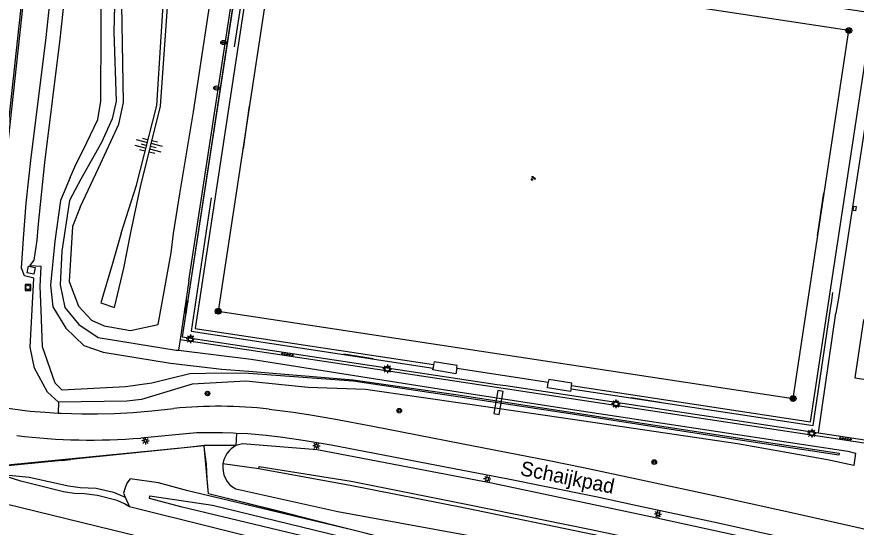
# Model space of a CAD drawing. Extents: x 125000 to 129004, y 397500 to 399008.
# Drawn here: x 126193.2 to 126337.5, y 398746.2 to 398833.9 of the extents above; entities that cross this region are included whole.
import ezdxf

# ---------------------------------------------------------------- set-up
doc = ezdxf.new("R2010")
doc.units = 0
for name, color, linetype in [('bs-afsc-ballenvanger', 7, 'Continuous'), ('bs-afsc-belijning', 7, 'Continuous'), ('bs-afsc-doel', 7, 'Continuous'), ('bs-afsc-hekwerk laag', 7, 'Continuous'), ('bs-afsc-poort', 7, 'Continuous'), ('bs-symb-cornervlag', 7, 'Continuous'), ('bs-symb-veldverlichting', 7, 'Continuous'), ('gg-afsc-hekwerk', 7, 'Continuous'), ('gg-anno-openbare ruimte label', 7, 'Continuous'), ('gg-aspt-spoorlijn', 7, 'Continuous'), ('gg-bbg-overig bouwwerk', 7, 'Continuous'), ('gg-knt-BGT kruinlijn', 7, 'Continuous'), ('gg-knt-bovenkant onderkant talud', 7, 'Continuous'), ('gg-knt-verharding', 7, 'Continuous'), ('gg-kntw-bovenkant insteek waterloop', 7, 'Continuous'), ('gg-kntw-waterlijn', 7, 'Continuous'), ('gg-kwrk-kunstwerk', 7, 'Continuous'), ('gg-kwrk-kunstwerk niveau 01', 7, 'Continuous'), ('gg-kwrk-uitstroombak niveau min 01', 7, 'Continuous'), ('gt-grn-groengrens', 7, 'Continuous'), ('gt-symb-boom', 7, 'Continuous'), ('gt-symb-drainageput', 7, 'Continuous'), ('gt-symb-groenvak', 7, 'Continuous'), ('gt-symb-kolk center center', 7, 'Continuous'), ('gt-symb-lichtmast', 7, 'Continuous'), ('gt-symb-rioolschacht', 7, 'Continuous'), ('gt-symb-talud symbool', 7, 'Continuous'), ('gt-symb-tegel verharding', 7, 'Continuous'), ('gx-grn-maaiveld', 7, 'Continuous')]:
    doc.layers.add(name, color=color, linetype=linetype)

# ---------------------------------------------------------------- blocks, each defined once
blk = doc.blocks.new('bs0-CORNVLG')
at = {"layer": 'bs-symb-cornervlag'}
for p, q in [((-0.34, 0.2), (0.2, -0.34)), ((-0.21, 0.35), (0.34, -0.2)), ((0.03, 0.4), (0.4, 0.03)), ((-0.4, -0.03), (-0.03, -0.4))]:
    blk.add_line(p, q, dxfattribs=at)
blk.add_circle((0, 0), 0.5, dxfattribs=at)
blk = doc.blocks.new('bs0-VELDV')
at = {"layer": 'bs-symb-veldverlichting'}
for p, q in [((-0.38, 0), (-0.75, 0)), ((-0.53, 0.53), (-0.27, 0.27)), ((-0.35, 0.14), (-0.52, 0.22)), ((-0.22, 0.52), (-0.14, 0.35)), ((0, 0.75), (0, 0.38)), ((0.22, 0.52), (0.14, 0.35)), ((0.27, 0.27), (0.53, 0.53)), ((0.35, 0.14), (0.52, 0.22)), ((0.38, 0), (0.75, 0)), ((-0.27, -0.27), (-0.53, -0.53)), ((-0.35, -0.14), (-0.52, -0.22)), ((-0.14, -0.35), (-0.22, -0.52)), ((0, -0.38), (0, -0.75)), ((0.14, -0.35), (0.22, -0.52)), ((0.27, -0.27), (0.53, -0.53)), ((0.35, -0.14), (0.52, -0.22))]:
    blk.add_line(p, q, dxfattribs=at)
blk.add_circle((0, 0), 0.375, dxfattribs=at)
blk = doc.blocks.new('gt0-TEG1')
at = {"layer": 'gt-symb-tegel verharding'}
for p, q in [((-1.12, 0), (1.12, 0)), ((-0.9, -0.25), (-0.9, 0.25)), ((-0.45, -0.25), (-0.45, 0.25)), ((0, -0.25), (0, 0.25)), ((0.45, -0.25), (0.45, 0.25)), ((0.9, -0.25), (0.9, 0.25))]:
    blk.add_line(p, q, dxfattribs=at)
blk = doc.blocks.new('gt0-KOLKCC')
at = {"layer": 'gt-symb-kolk center center'}
blk.add_lwpolyline([(-0.38, 0.2), (0.37, 0.2), (0.37, -0.2), (-0.38, -0.2)], close=True, dxfattribs=at)
blk = doc.blocks.new('gt0-GRVAK')
at = {"layer": 'gt-symb-groenvak'}
for p, q in [((-0.11, 0.19), (-0.23, 0.24)), ((-0.18, 0.15), (0.09, 0.15)), ((-0.09, 0.21), (-0.16, 0.32)), ((-0.05, 0.21), (-0.05, 0.39)), ((0, 0.21), (0.06, 0.32)), ((0.01, 0.19), (0.13, 0.24)), ((0.26, -0.05), (0.2, 0.06)), ((0.3, -0.05), (0.3, 0.13)), ((0.35, -0.05), (0.41, 0.06)), ((-0.24, -0.23), (-0.36, -0.18)), ((-0.32, -0.26), (-0.05, -0.26)), ((-0.23, -0.21), (-0.29, -0.09)), ((-0.18, -0.2), (-0.18, -0.02)), ((-0.14, -0.21), (-0.07, -0.09)), ((-0.12, -0.23), (0, -0.18)), ((0.24, -0.07), (0.12, -0.02)), ((0.17, -0.11), (0.44, -0.11)), ((0.37, -0.07), (0.49, -0.02))]:
    blk.add_line(p, q, dxfattribs=at)
blk = doc.blocks.new('gt0-LMAST')
at = {"layer": 'gt-symb-lichtmast'}
for p, q in [((-0.18, 0.17), (-0.45, 0.44)), ((-0.01, 0.25), (-0.01, 0.62)), ((0.17, 0.17), (0.44, 0.44)), ((-0.26, 0), (-0.63, 0)), ((-0.18, -0.18), (-0.45, -0.45)), ((-0.01, -0.25), (-0.01, -0.63)), ((0.44, -0.45), (0.17, -0.18)), ((0.24, 0), (0.62, 0))]:
    blk.add_line(p, q, dxfattribs=at)
blk.add_circle((-0.01, 0), 0.25, dxfattribs=at)
blk = doc.blocks.new('gt0-BOOM')
at = {"layer": 'gt-symb-boom'}
for radius in [0.4, 0.2]:
    blk.add_circle((0, 0), radius, dxfattribs=at)
blk = doc.blocks.new('gt0-DPUT')
at = {"layer": 'gt-symb-drainageput'}
for p, q in [((-0.25, 0.05), (0.25, 0.05)), ((0.24, -0.05), (-0.25, -0.05))]:
    blk.add_line(p, q, dxfattribs=at)
for centre, radius, start, end in [((-0.25, 0), 0.0542, 85.4775, 270), ((0.24, 0), 0.0543, 269.9965, 85.474)]:
    blk.add_arc(centre, radius, start, end, dxfattribs=at)
blk.add_ellipse((0, 0), major_axis=(0.502, 0), ratio=0.705307, dxfattribs=at)
blk = doc.blocks.new('gt0-RS')
at = {"layer": 'gt-symb-rioolschacht'}
blk.add_lwpolyline([(-0.5, -0.5), (0.5, -0.5), (0.5, 0.5), (-0.5, 0.5)], close=True, dxfattribs=at)
blk.add_circle((0, 0), 0.375, dxfattribs=at)
blk = doc.blocks.new('gt0-TALUD_1')
at = {"layer": 'gt-symb-talud symbool'}
for p, q in [((-1, -1), (-1, 0)), ((-0.5, -2), (-0.5, 0)), ((0, -1), (0, 0)), ((0.5, -2), (0.5, 0)), ((1, -1), (1, 0))]:
    blk.add_line(p, q, dxfattribs=at)

msp = doc.modelspace()

# ---------------------------------------------------------------- linework, layer by layer
at = {"layer": 'bs-afsc-ballenvanger'}
msp.add_line((126341.93, 398834.46), (126334.44, 398785.6), dxfattribs=at)
for points in [[(126233, 398853.21), (126221.64, 398778.96), (126275.77, 398770.77)], [(126277.25, 398770.55), (126330.99, 398762.42), (126333.99, 398783.02)]]:
    msp.add_lwpolyline(points, dxfattribs=at)
at = {"layer": 'bs-afsc-belijning'}
msp.add_lwpolyline([(126237.42, 398846.56), (126227.83, 398783.32), (126326.65, 398768.33), (126336.23, 398831.55), (126237.42, 398846.56)], dxfattribs=at)
at = {"layer": 'bs-afsc-doel'}
for p, q in [((126233.16, 398818.61), (126232.1, 398811.22)), ((126330.82, 398796.27), (126331.94, 398803.64)), ((126249.44, 398776), (126254.46, 398775.23)), ((126298.81, 398768.51), (126303.82, 398767.74))]:
    msp.add_line(p, q, dxfattribs=at)
at = {"layer": 'bs-afsc-hekwerk laag'}
for p, q in [((126234.04, 398851.18), (126230.58, 398828.74)), ((126333.28, 398785.15), (126333.49, 398786.54))]:
    msp.add_line(p, q, dxfattribs=at)
for points in [[(126226.64, 398802.81), (126223.19, 398779.89), (126264.76, 398773.55)], [(126288.47, 398770.03), (126330.07, 398763.72), (126333.06, 398783.77)]]:
    msp.add_lwpolyline(points, dxfattribs=at)
at = {"layer": 'bs-afsc-poort'}
for p, q in [((126334.44, 398785.6), (126333.99, 398783.02)), ((126333.06, 398783.77), (126333.28, 398785.15)), ((126275.77, 398770.77), (126277.25, 398770.55))]:
    msp.add_line(p, q, dxfattribs=at)
at = {"layer": 'gg-afsc-hekwerk'}
for p, q in [((126275.77, 398770.77), (126277.25, 398770.55)), ((126277.25, 398770.55), (126330.99, 398762.42)), ((126330.99, 398762.42), (126345.75, 398760.19)), ((126200.93, 398757.68), (126189.65, 398756.6)), ((126200.93, 398757.68), (126202.46, 398757.84))]:
    msp.add_line(p, q, dxfattribs=at)
for points in [[(126232.95, 398852.87), (126221.64, 398778.96), (126275.77, 398770.77)], [(126478.28, 398689.43), (126382.65, 398712.62), (126375.31, 398714.47), (126360.52, 398718.07), (126336.14, 398724.04), (126326.36, 398726.54), (126319.09, 398728.39), (126311.75, 398730.28), (126304.45, 398732.15), (126294.67, 398734.65), (126287.33, 398736.48), (126279.99, 398738.36), (126272.66, 398740.23), (126265.31, 398742.09), (126257.97, 398743.95), (126253.08, 398745.2), (126226.17, 398751.99), (126225.41, 398760.23), (126216.76, 398759.33), (126189.21, 398756.69), (126182.23, 398757.51), (126178.71, 398758.29)], [(126225.4, 398760.25), (126222.61, 398759.9), (126202.46, 398757.84)], [(126250.04, 398745.96), (126245.76, 398747.04), (126238.41, 398748.92), (126226.18, 398751.99), (126225.95, 398754.54), (126225.84, 398757.09), (126225.48, 398759.56), (126225.4, 398760.25)]]:
    msp.add_lwpolyline(points, dxfattribs=at)
at = {"layer": 'gg-aspt-spoorlijn'}
msp.add_lwpolyline([(126178.19, 398753.48), (126243.65, 398737.46), (126261.2, 398733.1), (126493.41, 398676.34), (126551.44, 398662.05), (126716.84, 398621.64), (126769.51, 398608.68), (126782.19, 398605.65), (126808.74, 398599.06), (126873.68, 398583.16), (126950.77, 398564.39)], dxfattribs=at)
at = {"layer": 'gg-bbg-overig bouwwerk'}
for p, q in [((126264.86, 398774.16), (126264.76, 398773.55)), ((126288.47, 398770.03), (126288.55, 398770.56))]:
    msp.add_line(p, q, dxfattribs=at)
for points in [[(126268.83, 398773.56), (126268.9, 398774), (126264.94, 398774.66), (126264.86, 398774.16)], [(126268.83, 398773.56), (126268.67, 398772.58), (126264.71, 398773.24), (126264.76, 398773.55)], [(126288.47, 398770.03), (126288.41, 398769.56), (126284.42, 398770.17), (126284.57, 398771.17)], [(126288.55, 398770.56), (126288.61, 398771), (126284.63, 398771.61), (126284.57, 398771.17)]]:
    msp.add_lwpolyline(points, dxfattribs=at)
at = {"layer": 'gg-knt-BGT kruinlijn'}
for p, q in [((126193.9, 398754.12), (126190.08, 398755.35)), ((126201.24, 398752.33), (126193.9, 398754.12)), ((126203.09, 398752.05), (126201.24, 398752.33)), ((126204.8, 398751.95), (126203.09, 398752.05)), ((126207.08, 398751.66), (126204.8, 398751.95)), ((126210.45, 398750.8), (126207.08, 398751.66)), ((126211.72, 398750.25), (126210.45, 398750.8)), ((126212.58, 398749.74), (126211.72, 398750.25))]:
    msp.add_line(p, q, dxfattribs=at)
for points in [[(126211.12, 398796.76), (126213.8, 398804.98), (126217.29, 398818.65), (126218.75, 398842.29), (126220.71, 398866.08), (126222.04, 398889.56), (126220.71, 398902.4), (126224.92, 398913.56), (126230.87, 398934.16), (126235.52, 398952.3), (126240.11, 398970.7), (126244.21, 398993.87), (126245.36, 399000)], [(126212.79, 398796.85), (126214.45, 398804.72), (126217.92, 398818.54), (126219.55, 398842.15), (126221.57, 398866.06), (126224.03, 398889.12), (126224.94, 398901.72), (126227.27, 398913.12), (126232.02, 398933.76), (126236.66, 398952.06), (126241, 398970.48), (126244.91, 398993.71), (126246.02, 399000)], [(126211.12, 398796.76), (126209.64, 398791.51), (126207.68, 398784.77), (126209.98, 398783.96), (126211.6, 398790.71), (126212.79, 398796.85)], [(126234.8, 398756.28), (126234.87, 398756.68), (126250.69, 398754.16), (126270.45, 398750.18), (126291.94, 398745.85), (126316.42, 398740.62), (126337.45, 398736.02), (126353.19, 398732.62)], [(126355.4, 398731.1), (126337, 398735.28), (126316.43, 398739.84), (126292.45, 398744.92), (126270.29, 398749.49), (126250.52, 398753.38), (126234.8, 398756.28)]]:
    msp.add_lwpolyline(points, dxfattribs=at)
at = {"layer": 'gg-knt-bovenkant onderkant talud'}
for points in [[(126204.12, 398801.18), (126207.27, 398807.9), (126210.77, 398815.47), (126211.54, 398819.18), (126211.15, 398842.84), (126211.31, 398866.36), (126211.15, 398890.1), (126212.52, 398897.68), (126212.58, 398906.21), (126215.25, 398916.33), (126222.46, 398935.51), (126224.93, 398943.33), (126228.92, 398954.45), (126234.85, 398971.83), (126239.51, 398995.23), (126240.48, 399000)], [(126220.17, 398796.67), (126221.21, 398803.52), (126223.59, 398817.57), (126227.06, 398840.65), (126230.5, 398865.35), (126232.89, 398887.78), (126236.04, 398900.78), (126237.19, 398911.52), (126240.04, 398932.3), (126243.4, 398950.47), (126246, 398969.2), (126249.56, 398992.89), (126250.56, 399000)], [(126204.12, 398801.18), (126202.79, 398797.9), (126202.2, 398788.46), (126203.81, 398784.2), (126206.02, 398781.77), (126208.24, 398780.84), (126212.74, 398780.05), (126217.53, 398781.03), (126219.73, 398793.36), (126220.17, 398796.67)], [(126244.83, 398759.55), (126232.01, 398760.58), (126230.88, 398760.27)], [(126535.96, 398691.59), (126505.88, 398699.05), (126477.56, 398706.3), (126448.07, 398713.65), (126418.96, 398720.83), (126390.64, 398727.33), (126361.54, 398734.7), (126333.39, 398741.18), (126303.24, 398747.81), (126274.8, 398753.78), (126244.83, 398759.55)], [(126230.83, 398752.81), (126248.38, 398748.91), (126275.65, 398743.95), (126299.64, 398739.08), (126327.07, 398733.22), (126355.09, 398727.05)]]:
    msp.add_lwpolyline(points, dxfattribs=at)
for centre, radius, start, end in [((126232.83, 398756.52), 4.23, 117.5309, 171.6776), ((126232.82, 398756.53), 4.22, 171.7189, 241.8871)]:
    msp.add_arc(centre, radius, start, end, dxfattribs=at)
at = {"layer": 'gg-knt-verharding'}
for p, q in [((126222.75, 398788.53), (126232.6, 398852.93)), ((126222.75, 398788.53), (126221.28, 398778.49)), ((126268.83, 398773.56), (126284.57, 398771.17))]:
    msp.add_line(p, q, dxfattribs=at)
for points in [[(126288.55, 398770.56), (126329.61, 398764.32), (126340.28, 398834.5), (126234.52, 398850.57), (126223.87, 398780.39), (126264.86, 398774.16)], [(126348.79, 398780.35), (126338.73, 398781.87), (126337.25, 398771.91), (126347.29, 398770.39)], [(126221.28, 398778.49), (126266.93, 398771.6), (126345.67, 398759.67), (126345.67, 398759.7)], [(126186.22, 398767.91), (126188.57, 398767.33), (126190.42, 398766.93), (126192.12, 398766.61), (126194.21, 398766.31), (126195.51, 398766.16), (126198.07, 398765.97), (126200.33, 398765.85)], [(126200.33, 398765.85), (126200.84, 398765.83), (126204.41, 398765.72), (126207.09, 398765.72), (126209.99, 398765.78), (126213.15, 398765.96), (126216.4, 398766.24), (126220.21, 398766.62)], [(126236.6, 398766.51), (126240.73, 398766), (126243.36, 398765.62), (126247.68, 398764.86), (126254.41, 398763.58), (126269.66, 398760.64), (126284.74, 398757.67), (126290.61, 398756.47), (126299.75, 398754.55), (126314.67, 398751.35), (126328.46, 398748.3), (126338.37, 398746.09), (126340.49, 398745.57), (126357.83, 398741.65)], [(126230.96, 398762.35), (126230.4, 398762.38), (126228.59, 398762.42), (126224.09, 398762.42), (126214.54, 398761.55)], [(126356.77, 398737.24), (126352.15, 398738.33), (126338.98, 398741.34), (126327.09, 398743.98), (126313.78, 398746.91), (126299.02, 398750.1), (126293, 398751.37), (126283.61, 398753.29), (126277.67, 398754.48), (126268.39, 398756.29), (126247.22, 398760.33), (126242.75, 398761.08), (126238.93, 398761.65), (126236.06, 398761.99), (126232.94, 398762.26), (126230.96, 398762.35)]]:
    msp.add_lwpolyline(points, dxfattribs=at)
for centre, radius, start, end in [((126227.89, 398688.62), 78.38, 83.6252, 95.6266), ((126205.96, 398867.58), 106.37, 263.1025, 274.6283)]:
    msp.add_arc(centre, radius, start, end, dxfattribs=at)
at = {"layer": 'gg-kntw-bovenkant insteek waterloop'}
for points in [[(126194.82, 398801.92), (126195.6, 398809.24), (126198.28, 398830.35), (126200.6, 398852.35), (126202.6, 398870.53), (126205.11, 398890.25), (126205.86, 398898.74), (126207.18, 398909.1), (126207.54, 398916.03), (126209.09, 398923.11), (126212.27, 398936.35), (126215.29, 398950.37), (126218.62, 398972.72), (126222.13, 398994.95), (126222.9, 399000)], [(126220.43, 398934.4), (126219.54, 398931.42), (126216.45, 398922.19), (126214.2, 398916.33), (126212.1, 398908.85), (126211.16, 398906.68), (126211, 398902.92), (126211.53, 398899.33), (126211.08, 398897.23), (126209.87, 398890.85), (126209.95, 398870.87), (126210.44, 398853.87), (126209.89, 398831.34), (126210.31, 398819.41), (126209.59, 398816.36), (126207.78, 398812.31), (126204.23, 398806.02)], [(126204.23, 398806.02), (126202.26, 398802.33), (126200.95, 398793.63), (126200.66, 398787.87), (126201.45, 398783.99), (126203.88, 398781.05), (126207.2, 398778.82), (126220.61, 398776.66), (126221, 398776.62)], [(126200.4, 398767.72), (126198.49, 398769.42), (126196.27, 398773.56), (126195.53, 398777.18), (126196.11, 398789.01), (126194.54, 398789.42), (126193.99, 398790.74), (126194.38, 398795.82), (126194.82, 398801.92)], [(126221, 398776.62), (126233.49, 398775.09), (126251.27, 398772.32), (126269.08, 398769.46), (126289.45, 398766.34), (126336.08, 398759.27), (126337.35, 398758.96)], [(126337.35, 398758.96), (126337.1, 398756.86), (126332.57, 398757.81), (126317.1, 398760.56), (126288.73, 398764.75), (126270.7, 398767.36), (126253.15, 398769.87), (126243.3, 398770.23), (126232.59, 398771.32), (126223.36, 398770.8), (126214.64, 398768.17), (126212.1, 398767.89), (126200.4, 398767.72)]]:
    msp.add_lwpolyline(points, dxfattribs=at)
at = {"layer": 'gg-kntw-waterlijn'}
for points in [[(126196.93, 398798.36), (126198, 398808.89), (126200.69, 398830.06), (126202.99, 398851.76), (126204.83, 398870.42), (126207.04, 398890.34), (126207.7, 398898.07), (126208.71, 398908.69), (126209.56, 398916.5), (126211, 398922.5), (126214.32, 398935.67), (126217.53, 398950.17), (126221, 398972.49), (126224.24, 398994.42), (126225.1, 399000)], [(126202.36, 398806.29), (126203.19, 398808.13), (126205.26, 398812.3), (126207.15, 398816.29), (126207.63, 398819.39), (126207.72, 398831.87), (126207.75, 398853.51)], [(126202.36, 398806.29), (126200.72, 398802.37), (126199.73, 398795.36), (126199, 398787.82), (126199.38, 398784.09), (126201.63, 398780.44), (126204.72, 398777.47), (126208.08, 398776.32), (126219.61, 398774.43), (126228.46, 398773.36), (126233.08, 398773.06), (126251.03, 398771.56), (126269.05, 398768.96), (126289.14, 398765.9), (126317.49, 398761.54), (126334.59, 398758.95), (126334.5, 398758.61), (126317.15, 398761.26), (126289.07, 398765.61), (126269.04, 398768.64), (126251.01, 398771.31), (126233.04, 398772.62), (126228.41, 398772.68), (126222.93, 398772.56), (126216.43, 398770.97), (126211.88, 398770.34), (126200.99, 398769.77), (126199.81, 398770.99), (126197.65, 398777.2), (126197.4, 398783.5), (126197.22, 398787.57), (126197.41, 398791.03), (126195.43, 398791.1), (126196.17, 398792.12), (126196.73, 398795.52), (126196.93, 398798.36)]]:
    msp.add_lwpolyline(points, dxfattribs=at)
at = {"layer": 'gg-kwrk-kunstwerk'}
for points in [[(126202.09, 398910.96), (126202.38, 398910.9), (126188.46, 398783.21), (126186.17, 398778.21), (126184.26, 398773.61), (126182.75, 398769.58), (126183.47, 398769.38), (126183.39, 398769.11)], [(126201.22, 398903.16), (126188.17, 398783.25), (126186.61, 398779.94), (126184.59, 398775.28), (126182.65, 398770.25), (126182.35, 398769.37)]]:
    msp.add_lwpolyline(points, dxfattribs=at)
at = {"layer": 'gg-kwrk-kunstwerk niveau 01'}
msp.add_lwpolyline([(126275.21, 398765.74), (126276.14, 398765.6), (126276.79, 398769.53), (126275.87, 398769.69), (126275.21, 398765.74)], dxfattribs=at)
at = {"layer": 'gg-kwrk-uitstroombak niveau min 01'}
msp.add_lwpolyline([(126196.13, 398789.67), (126195, 398789.92), (126195.23, 398791.06), (126196.36, 398790.82), (126196.13, 398789.67)], dxfattribs=at)
at = {"layer": 'gt-grn-groengrens'}
for p, q in [((126221.28, 398778.49), (126221, 398776.62)), ((126200.4, 398767.72), (126200.33, 398765.85)), ((126230.96, 398762.35), (126230.88, 398760.27)), ((126230.88, 398760.27), (126225.4, 398760.25)), ((126234.8, 398756.28), (126228.65, 398757.14))]:
    msp.add_line(p, q, dxfattribs=at)
at = {"layer": 'gx-grn-maaiveld'}
msp.add_line((126211.85, 398751.4), (126212.58, 398749.74), dxfattribs=at)
for points in [[(126190.08, 398755.35), (126195.35, 398754.85), (126202.12, 398753.33), (126204.12, 398753.07), (126206.84, 398752.93), (126209.84, 398752.25), (126211.85, 398751.4)], [(126250.04, 398745.96), (126229.57, 398750.85), (126222.62, 398752.51), (126217.55, 398753.85), (126212.7, 398754.54), (126212.1, 398753.81), (126211.75, 398752.83), (126211.57, 398752.09), (126211.85, 398751.4)], [(126517.5, 398677.81), (126400.31, 398706.6), (126396.8, 398707.75), (126383.6, 398710.91), (126345.98, 398719.92), (126221.62, 398749.69), (126215.99, 398751.17), (126216.09, 398751.6), (126226.82, 398750.05), (126299.12, 398732.42), (126344.55, 398721.2), (126389.27, 398710.39), (126397.11, 398708.43), (126402.23, 398706.92), (126472.7, 398689.7)], [(126447.8, 398692.22), (126400.21, 398704.18), (126397.78, 398705.12), (126395.55, 398705.69), (126391.78, 398706.03), (126354.41, 398714.97), (126330.23, 398721.78), (126327.03, 398722.31), (126313.03, 398725.11), (126279.84, 398733.33), (126276.86, 398734.35), (126275.53, 398734.71), (126273.76, 398734.91), (126271.08, 398735.36), (126241.58, 398742.51), (126212.58, 398749.74)]]:
    msp.add_lwpolyline(points, dxfattribs=at)

# ---------------------------------------------------------------- block references
at = {"layer": 'bs-symb-cornervlag'}
for p in [(126336.23, 398831.55), (126227.83, 398783.32), (126326.65, 398768.33)]:
    msp.add_blockref('bs0-CORNVLG', p, dxfattribs=at)
at = {"layer": 'bs-symb-veldverlichting'}
for p in [(126223.08, 398778.57), (126256.9, 398773.42), (126296.18, 398767.41), (126329.85, 398762.37)]:
    msp.add_blockref('bs0-VELDV', p, dxfattribs=at)
at = {"layer": 'gt-symb-boom'}
for p in [(126225.99, 398769.2), (126258.94, 398766.25), (126302.77, 398757.43)]:
    msp.add_blockref('gt0-BOOM', p, dxfattribs=at)
at = {"layer": 'gt-symb-drainageput'}
for p in [(126228.76, 398829.48), (126227.55, 398821.67)]:
    msp.add_blockref('gt0-DPUT', p, dxfattribs=at)
at = {"layer": 'gt-symb-groenvak'}
msp.add_blockref('gt0-GRVAK', (126281.94, 398806.16), dxfattribs=at)
at = {"layer": 'gt-symb-kolk center center', "rotation": 81.43241009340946}
msp.add_blockref('gt0-KOLKCC', (126337.22, 398801), dxfattribs=at)
at = {"layer": 'gt-symb-lichtmast'}
for p in [(126215.34, 398761.06), (126244.72, 398760.21), (126274.08, 398754.52), (126303.43, 398748.47)]:
    msp.add_blockref('gt0-LMAST', p, dxfattribs=at)
at = {"layer": 'gt-symb-rioolschacht'}
msp.add_blockref('gt0-RS', (126195.12, 398787.41), dxfattribs=at)
at = {"layer": 'gt-symb-talud symbool'}
for p, xscale, yscale, rotation in [((126215.54, 398811.82), 0.9997619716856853, 0.9997619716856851, -104.48103437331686), ((126216.19, 398811.63), 1.0002204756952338, 1.0002204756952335, 76.11658196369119)]:
    msp.add_blockref('gt0-TALUD_1', p, dxfattribs=dict(at, xscale=xscale, yscale=yscale, rotation=rotation))
at = {"layer": 'gt-symb-tegel verharding'}
for p, rotation in [((126222.31, 398784.07), 80.97080115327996), ((126239.73, 398775.92), -8.397572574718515), ((126335.65, 398761.44), -8.219209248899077)]:
    msp.add_blockref('gt0-TEG1', p, dxfattribs=dict(at, rotation=rotation))

# ---------------------------------------------------------------- texts
at = {"layer": 'gg-anno-openbare ruimte label'}
msp.add_text('Schaijkpad', height=2.5, rotation=348.6, dxfattribs=at).set_placement((126279.61, 398755.2))

doc.saveas('drawing.dxf')
